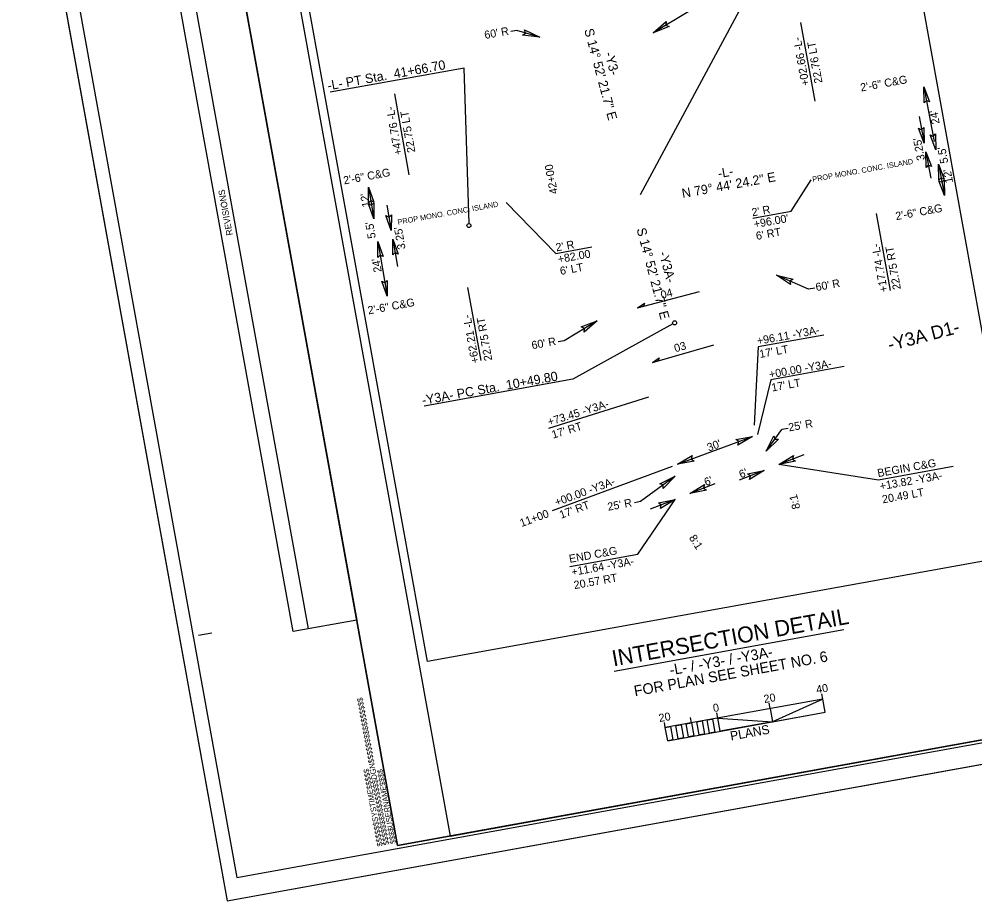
# Model space of a CAD drawing. Extents: x 1620721 to 1621526, y 897852 to 898403.
# Drawn here: x 1620721.2 to 1621079.6, y 897851.9 to 898182.7 of the extents above; entities that cross this region are included whole.
import ezdxf

# ---------------------------------------------------------------- set-up
doc = ezdxf.new("R2010")
doc.units = 0
for name, color, linetype in [('Default', 7, 'Continuous'), ('Prop Conc 2ft 6in Curb and Gutter', 7, 'Continuous'), ('Prop Dimension', 7, 'Continuous'), ('Prop DSN Text', 7, 'Continuous'), ('Prop Horizontal Alignment Direction Label', 7, 'Continuous'), ('Prop Horizontal Alignment Station Label', 7, 'Continuous'), ('Prop Superelevation  Arrow CELL', 7, 'Continuous'), ('Prop Terminator CELL', 7, 'Continuous'), ('Sheet Block Revision CELL', 7, 'Continuous'), ('Sheet Clip Boundary CELL', 7, 'Continuous'), ('Sheet Cutting Line CELL', 7, 'Continuous'), ('Sheet Data Field CELL', 7, 'Continuous'), ('Sheet Layout Plan Border', 7, 'Continuous'), ('Sheet Plan CELL', 7, 'Continuous'), ('Sheet Plot Border Inside CELL', 7, 'Continuous'), ('Sheet Plot Border Outside CELL', 7, 'Continuous'), ('Sheet Title CELL', 7, 'Continuous')]:
    doc.layers.add(name, color=color, linetype=linetype)

msp = doc.modelspace()

# ---------------------------------------------------------------- linework, layer by layer
at = {"layer": 'Default'}
msp.add_line((1620944.38, 897938.1), (1621030.49, 897953.68), dxfattribs=at)
at = {"layer": 'Prop Conc 2ft 6in Curb and Gutter'}
for p, q in [((1621014.24, 898181.38), (1621019.59, 898151.82)), ((1620861.93, 898154.63), (1620867.28, 898124.28)), ((1621010.71, 898110.55), (1621018.16, 898122.33)), ((1620922.41, 898094.77), (1620903.85, 898113.83)), ((1620996.35, 898107.95), (1621010.71, 898110.55)), ((1621042.54, 898109.72), (1621047.77, 898080.81)), ((1620922.41, 898094.77), (1620936, 898097.23)), ((1620894.4, 898054.57), (1620889.47, 898082.01)), ((1621022.95, 898064.14), (1620998.31, 898059.68)), ((1620998.31, 898059.68), (1620996.79, 898030.3)), ((1621030.58, 898052.31), (1621003.08, 898047.33)), ((1621003.08, 898047.33), (1620998.08, 898026.77)), ((1620919.88, 898029.17), (1620957.34, 898040.91)), ((1621043.42, 898009.73), (1621006.12, 898015.57)), ((1620921.18, 897998.37), (1620966.19, 898014.99)), ((1621071.44, 898014.8), (1621043.42, 898009.73)), ((1620953.25, 897981.91), (1620967.15, 898002.45)), ((1620927.76, 897977.3), (1620953.25, 897981.91))]:
    msp.add_line(p, q, dxfattribs=at)
at = {"layer": 'Prop Dimension'}
for p, q in [((1620972.27, 898185.47), (1620959, 898177.55)), ((1620907.88, 898178.38), (1620905.6, 898177.97)), ((1620916.4, 898175.87), (1620907.88, 898178.38)), ((1621060.47, 898157.21), (1621064.32, 898136.78)), ((1621058.69, 898146.07), (1621060.57, 898136.1)), ((1621061.18, 898132.91), (1621063.05, 898122.97)), ((1621065.94, 898128.22), (1621068.16, 898116.43)), ((1620852.16, 898119.62), (1620854.2, 898107.79)), ((1620859.13, 898112.85), (1620860.76, 898103.34)), ((1620855.68, 898099.17), (1620859.2, 898078.72)), ((1620861.32, 898100.14), (1620863.09, 898089.84)), ((1621017.25, 898081.3), (1621005.14, 898086.57)), ((1621019.53, 898081.72), (1621017.25, 898081.3)), ((1620937.95, 898069.51), (1620925.58, 898061.98)), ((1620925.58, 898061.98), (1620923.3, 898061.57)), ((1620968.06, 898015.68), (1620996.21, 898026.07)), ((1621001.3, 898020.62), (1621007.25, 898028.69)), ((1621009.53, 898029.11), (1621007.25, 898028.69)), ((1621015.42, 898019.23), (1621006.12, 898015.57)), ((1621000.53, 898013.36), (1620991.23, 898009.69)), ((1620967.17, 898011.19), (1620954.23, 898001.65)), ((1620982.04, 898008.32), (1620972.74, 898004.66)), ((1620954.23, 898001.65), (1620951.95, 898001.23)), ((1620967.15, 898002.45), (1620957.85, 897998.78))]:
    msp.add_line(p, q, dxfattribs=at)
at = {"layer": 'Prop DSN Text'}
msp.add_lwpolyline([(1620818.11, 898252.36), (1621041.11, 898292.72), (1621097.35, 897981.99), (1620874.36, 897941.62)], close=True, dxfattribs=at)
at = {"layer": 'Prop Horizontal Alignment Station Label'}
for p, q in [((1620954.2, 898116.85), (1620994.9, 898192.6)), ((1620888.12, 898164.31), (1620837.89, 898155.22)), ((1620889.97, 898105.94), (1620888.12, 898164.31)), ((1620966.33, 898068.35), (1620928.86, 898047.53)), ((1620928.86, 898047.53), (1620873.07, 898037.43))]:
    msp.add_line(p, q, dxfattribs=at)
for centre in [(1620889.86, 898105.2), (1620966.99, 898068.72)]:
    msp.add_circle(centre, 0.75, dxfattribs=at)
at = {"layer": 'Prop Superelevation  Arrow CELL'}
for p, q in [((1620953.07, 898074.36), (1620976.27, 898080.52)), ((1620958.66, 898053.84), (1620981.71, 898060.52))]:
    msp.add_line(p, q, dxfattribs=at)
for points in [[(1620953.07, 898074.36), (1620955.71, 898076.1), (1620955.3, 898074.96)], [(1620953.07, 898074.36), (1620955.71, 898076.1), (1620955.3, 898074.96)], [(1620958.66, 898053.84), (1620961.26, 898055.64), (1620960.88, 898054.49)], [(1620958.66, 898053.84), (1620961.26, 898055.64), (1620960.88, 898054.49)]]:
    msp.add_lwpolyline(points, close=True, dxfattribs=at)
at = {"layer": 'Prop Terminator CELL'}
for points in [[(1620964.96, 898179.85), (1620959, 898177.55), (1620963.86, 898181.76), (1620963.75, 898180.39)], [(1620910.66, 898178.69), (1620916.4, 898175.87), (1620910, 898176.59), (1620911.09, 898177.44)], [(1621060.56, 898151.27), (1621060.47, 898157.21), (1621062.58, 898151.62), (1621061.42, 898152.16)], [(1621060.48, 898142.04), (1621060.57, 898136.1), (1621058.46, 898141.69), (1621059.62, 898141.15)], [(1621064.82, 898139.56), (1621064.92, 898133.63), (1621062.8, 898139.21), (1621063.96, 898138.67)], [(1621061.27, 898126.97), (1621061.18, 898132.91), (1621063.29, 898127.32), (1621062.13, 898127.86)], [(1621066.03, 898122.29), (1621065.94, 898128.22), (1621068.05, 898122.63), (1621066.89, 898123.17)], [(1620852.16, 898113.68), (1620852.16, 898119.62), (1620854.19, 898114), (1620853.03, 898114.56)], [(1621068.07, 898122.36), (1621068.16, 898116.43), (1621066.05, 898122.02), (1621067.21, 898121.47)], [(1620854.2, 898113.73), (1620854.2, 898107.79), (1620852.18, 898113.41), (1620853.33, 898112.85)], [(1620860.77, 898109.28), (1620860.76, 898103.34), (1620858.74, 898108.97), (1620859.89, 898108.41)], [(1620855.68, 898093.23), (1620855.68, 898099.17), (1620857.7, 898093.55), (1620856.55, 898094.11)], [(1620861.31, 898094.21), (1620861.32, 898100.14), (1620863.34, 898094.52), (1620862.19, 898095.08)], [(1620859.2, 898084.65), (1620859.2, 898078.72), (1620857.18, 898084.34), (1620858.33, 898083.78)], [(1621010.49, 898083.06), (1621005.14, 898086.57), (1621011.4, 898085.07), (1621010.21, 898084.36)], [(1620932, 898067.16), (1620937.95, 898069.51), (1620933.12, 898065.26), (1620933.22, 898066.63)], [(1620989.92, 898024.91), (1620996.21, 898026.07), (1620990.65, 898022.83), (1620991.02, 898024.16)], [(1621005.91, 898025.04), (1621001.3, 898020.62), (1621004.16, 898026.38), (1621004.58, 898025.07)], [(1620974.35, 898016.84), (1620968.06, 898015.68), (1620973.62, 898018.93), (1620973.25, 898017.6)], [(1621012.38, 898016.87), (1621006.12, 898015.57), (1621011.6, 898018.93), (1621011.26, 898017.59)], [(1620994.27, 898012.06), (1621000.53, 898013.36), (1620995.05, 898010), (1620995.39, 898011.33)], [(1620961.45, 898008.32), (1620967.17, 898011.19), (1620962.73, 898006.52), (1620962.72, 898007.9)], [(1620979, 898005.96), (1620972.74, 898004.66), (1620978.22, 898008.02), (1620977.88, 898006.68)], [(1620960.9, 898001.15), (1620967.15, 898002.45), (1620961.67, 897999.09), (1620962.01, 898000.42)]]:
    msp.add_lwpolyline(points, close=True, dxfattribs=at)
at = {"layer": 'Sheet Block Revision CELL'}
msp.add_line((1620829.72, 897953.94), (1620773.38, 898265.13), dxfattribs=at)
msp.add_lwpolyline([(1620823.99, 897952.89), (1620767.66, 898264.09), (1620791.49, 898268.42), (1620847.82, 897957.21)], close=True, dxfattribs=at)
at = {"layer": 'Sheet Clip Boundary CELL'}
msp.add_lwpolyline([(1620882.81, 897876.15), (1621433.86, 897975.9), (1621374.12, 898305.94), (1621299.62, 898292.45), (1621284.56, 898375.7), (1620808, 898289.43)], close=True, dxfattribs=at)
at = {"layer": 'Sheet Cutting Line CELL'}
for p, q in [((1620721.19, 898282.86), (1620799.2, 897851.87)), ((1620799.2, 897851.87), (1621461.84, 897971.81))]:
    msp.add_line(p, q, dxfattribs=at)
at = {"layer": 'Sheet Data Field CELL'}
msp.add_line((1621002.86, 897924.02), (1621002.51, 897925.98), dxfattribs=at)
at = {"layer": 'Sheet Layout Plan Border'}
msp.add_lwpolyline([(1620882.81, 897876.15), (1621433.86, 897975.9), (1621374.12, 898305.94), (1621299.62, 898292.45), (1621284.56, 898375.7), (1620808, 898289.43)], close=True, dxfattribs=at)
at = {"layer": 'Sheet Plan CELL'}
for p, q in [((1620788.48, 897951.55), (1620793.4, 897952.44)), ((1620863.13, 897872.59), (1620863.13, 897872.59))]:
    msp.add_line(p, q, dxfattribs=at)
for points in [[(1621378.74, 898392.74), (1620788.32, 898285.87), (1620863.13, 897872.59), (1621453.54, 897979.46)], [(1620863.13, 897872.59), (1620788.31, 898285.86), (1621299.99, 898378.49), (1621310.69, 898319.43), (1621389.42, 898333.68), (1621453.54, 897979.46)]]:
    msp.add_lwpolyline(points, close=True, dxfattribs=at)
at = {"layer": 'Sheet Plot Border Inside CELL'}
msp.add_lwpolyline([(1620802.89, 897860.66), (1621458.63, 897979.36), (1621383.47, 898394.61), (1620727.73, 898275.92)], close=True, dxfattribs=at)
at = {"layer": 'Sheet Plot Border Outside CELL'}
msp.add_lwpolyline([(1620799.2, 897851.87), (1621461.84, 897971.81), (1621383.82, 898402.8), (1620721.19, 898282.86)], close=True, dxfattribs=at)
at = {"layer": 'Sheet Title CELL'}
for p, q in [((1621022.54, 897927.58), (1621022.18, 897929.55)), ((1621022.54, 897927.58), (1620963.5, 897916.89)), ((1621002.86, 897924.02), (1621002.5, 897925.98)), ((1620964.39, 897911.97), (1621023.43, 897922.65)), ((1620983.18, 897920.45), (1620982.82, 897922.42)), ((1621002.86, 897924.02), (1621003.75, 897919.1)), ((1620963.5, 897916.89), (1620963.14, 897918.85)), ((1620973.34, 897918.67), (1620972.98, 897920.64))]:
    msp.add_line(p, q, dxfattribs=at)
for points in [[(1621022.54, 897927.58), (1621003.75, 897919.1), (1621023.43, 897922.65)], [(1620971.37, 897918.31), (1620973.34, 897918.67), (1620974.23, 897913.75), (1620972.26, 897913.4)], [(1620975.31, 897919.02), (1620977.27, 897919.38), (1620978.16, 897914.46), (1620976.2, 897914.11)], [(1620979.24, 897919.74), (1620981.21, 897920.1), (1620982.1, 897915.17), (1620980.13, 897914.82)], [(1620983.18, 897920.45), (1621003.75, 897919.1), (1620984.07, 897915.53)], [(1620963.5, 897916.89), (1620965.47, 897917.25), (1620966.36, 897912.33), (1620964.39, 897911.97)], [(1620967.43, 897917.6), (1620969.4, 897917.95), (1620970.29, 897913.03), (1620968.33, 897912.68)]]:
    msp.add_lwpolyline(points, close=True, dxfattribs=at)

# ---------------------------------------------------------------- texts
at = {"layer": 'Default'}
for s, height, p in [('INTERSECTION DETAIL', 6, (1620944.08, 897939.81)), ('FOR PLAN SEE SHEET NO. 6', 4, (1620952.13, 897928.6)), ('-L- / -Y3- / -Y3A-', 4, (1620965.45, 897936.46))]:
    msp.add_text(s, height=height, rotation=10.2599, dxfattribs=at).set_placement(p)
at = {"layer": 'Prop Conc 2ft 6in Curb and Gutter'}
for s, rotation, p in [('+02.66 -L-', 100.2599, (1621017.55, 898157.95)), ('22.76 LT', 100.2599, (1621022.47, 898158.84)), ('+47.76 -L-', 99.9888, (1620864.87, 898131.95)), ('22.75 LT', 99.9888, (1620869.8, 898132.82)), ("2' R", 10.2599, (1620996.18, 898108.65)), ("+96.00'", 10.2599, (1620996.98, 898104.23)), ("6' RT", 10.2599, (1620997.78, 898099.8)), ("2' R", 10.2599, (1620922.69, 898095.51)), ('+17.74 -L-', 100.2599, (1621046.96, 898080.53)), ('+82.00', 10.2599, (1620923.49, 898091.08)), ('22.75 RT', 100.2599, (1621051.88, 898081.42)), ("6' LT", 10.2599, (1620924.29, 898086.66)), ('+62.21 -L-', 100.2599, (1620893.72, 898053.85)), ('22.75 RT', 100.2599, (1620898.64, 898054.74)), ('+96.11 -Y3A-', 10.2599, (1620998.15, 898060.44)), ("17' LT", 10.2599, (1620999.04, 898055.52)), ('+00.00 -Y3A-', 10.2599, (1621002.7, 898047.86)), ("17' LT", 10.2599, (1621003.59, 898042.94)), ('+73.45 -Y3A-', 17.4099, (1620919.93, 898030.01)), ("17' RT", 17.4099, (1620921.43, 898025.24)), ('BEGIN C&G', 10.2599, (1621043.31, 898010.83)), ('+13.82 -Y3A-', 10.2599, (1621044.2, 898005.91)), ('+00.00 -Y3A-', 20.2689, (1620922.71, 897999.88)), ('20.49 LT', 10.2599, (1621045.1, 898000.99)), ("17' RT", 20.2689, (1620924.44, 897995.19)), ('END C&G', 10.2599, (1620927.69, 897978.66)), ('+11.64 -Y3A-', 10.2599, (1620928.58, 897973.74)), ('20.57 RT', 10.2599, (1620929.47, 897968.82))]:
    msp.add_text(s, height=3, rotation=rotation, dxfattribs=at).set_placement(p)
at = {"layer": 'Prop Dimension'}
for s, height, rotation, p in [("60' R", 3, 10.2599, (1620895.93, 898175.19)), ('2\'-6" C&G', 3, 10.3795, (1621036.93, 898155.47)), ("24'", 3, 100.6893, (1621066.39, 898143.55)), ("3.25'", 3, 100.6893, (1621060.89, 898129.91)), ("5.5'", 3, 100.6893, (1621069.62, 898128.77)), ('PROP MONO. CONC. ISLAND', 2, 10.2616, (1621018.82, 898121.55)), ('2\'-6" C&G', 3, 10.3795, (1620843.05, 898120.62)), ("12'", 3, 100.6893, (1621071.44, 898121.44)), ("12'", 3, 99.7628, (1620852.88, 898112.36)), ('PROP MONO. CONC. ISLAND', 2, 10.2616, (1620863.28, 898105.51)), ('2\'-6" C&G', 3, 10.3795, (1621050.11, 898107.23)), ("5.5'", 3, 99.7628, (1620854.96, 898100.58)), ("3.25'", 3, 99.7628, (1620866.13, 898096.52)), ("24'", 3, 99.7628, (1620857.19, 898087.92)), ("60' R", 3, 10.2599, (1621020.14, 898080.6)), ('2\'-6" C&G', 3, 10.3795, (1620852.23, 898071.88)), ("60' R", 3, 10.2599, (1620913.63, 898058.79)), ("25' R", 3, 10.2599, (1621009.93, 898027.97)), ("30'", 3, 20.2689, (1620979.79, 898020.41)), ("6'", 3, 21.5206, (1620991.85, 898010.33)), ("6'", 3, 21.5206, (1620978.78, 898007.43)), ('8:1', 3, 103.7993, (1621014.13, 897999.19)), ("25' R", 3, 10.2599, (1620942.11, 897998.22)), ('8:1', 3, 302.5465, (1620972.25, 897988.07))]:
    msp.add_text(s, height=height, rotation=rotation, dxfattribs=at).set_placement(p)
at = {"layer": 'Prop Horizontal Alignment Direction Label'}
for s, height, rotation, p in [('S 14%%d 52\' 21.7" E', 3.5, 284.8727, (1620933.07, 898178.63)), ('-Y3-', 3.5, 284.8727, (1620940.71, 898169.83)), ('-L-', 3.5, 10.2599, (1620983.55, 898122.97)), ('N 79%%d 44\' 24.2" E', 3.5, 10.2599, (1620970.03, 898115.52)), ('S 14%%d 52\' 21.7" E', 3.5, 284.8727, (1620952.7, 898103.87)), ('-Y3A-', 3.5, 284.8727, (1620961.05, 898094.97)), ('-Y3A D1-', 5, 14.6458, (1621047.64, 898058.08))]:
    msp.add_text(s, height=height, rotation=rotation, dxfattribs=at).set_placement(p)
at = {"layer": 'Prop Horizontal Alignment Station Label'}
for s, height, rotation, p in [('-L- PT Sta.  41+66.70', 3.5, 10.2599, (1620837.13, 898155.91)), ('42+00', 3, 100.2599, (1620923.2, 898117.31)), ('-Y3A- PC Sta.  10+49.80', 3.5, 10.2599, (1620872.59, 898037.93)), ('11+00', 3, 20.2689, (1620909.59, 897992.09))]:
    msp.add_text(s, height=height, rotation=rotation, dxfattribs=at).set_placement(p)
at = {"layer": 'Prop Superelevation  Arrow CELL'}
for s, rotation, p in [('04', 14.8727, (1620962.2, 898077.66)), ('03', 16.1593, (1620967.3, 898057.64))]:
    msp.add_text(s, height=3, rotation=rotation, dxfattribs=at).set_placement(p)
at = {"layer": 'Sheet Block Revision CELL'}
msp.add_text('REVISIONS', height=2.4, rotation=100.2599, dxfattribs=at).set_placement((1620801.32, 898101.7))
at = {"layer": 'Sheet Data Field CELL'}
for s, p in [('40', (1621020.36, 897929.63)), ('20', (1621000.68, 897926.06)), ('20', (1620961.32, 897918.94))]:
    msp.add_text(s, height=3, rotation=10.2599, dxfattribs=at).set_placement(p)
at = {"layer": 'Sheet Plan CELL'}
for s, p in [('$$$$$$$$$$$$$$$$DGN$$$$$$$$$$$$$$$$', (1620859.95, 897872.97)), ('$$$$$$SYSTIME$$$$$', (1620857.57, 897872.53)), ('$$$$USERNAME$$$$', (1620862.53, 897873.45))]:
    msp.add_text(s, height=2.1, rotation=100.26, dxfattribs=at).set_placement(p)
at = {"layer": 'Sheet Title CELL'}
for s, height, p in [('0', 3, (1620981.66, 897922.67)), ('PLANS', 3.4, (1620988.16, 897912))]:
    msp.add_text(s, height=height, rotation=10.2599, dxfattribs=at).set_placement(p)

doc.saveas('drawing.dxf')
